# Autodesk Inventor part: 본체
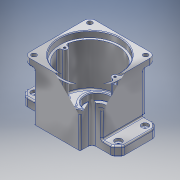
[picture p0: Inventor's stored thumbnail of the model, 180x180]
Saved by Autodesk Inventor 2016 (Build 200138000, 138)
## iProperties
Created: 2017-01
Part Number: 본체
Material: 알루미늄 6061
Document SubType Name: Modeling
Designer: Owner
Density: 2.7 g/cm^3
Appearance: 알루미늄 - 평지
Mass: 877.431 g
Surface Area: 768.445 cm^2
Volume: 324.975 cm^3
Author: Owner
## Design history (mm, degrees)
sketch "스케치1"
  geometry: L1 (-33, 47)-(33, 47); L2 (33, 47)-(33, -47); L3 (33, -47)-(-33, -47); L4 (-33, -47)-(-33, 47); L5 (-33, 47)-(33, -47); L6 (33, 47)-(-33, -47); 1 further point
  constraints: 12 end point, 2 midpoint, 2 parallel, 1 horizontal, 1 perpendicular
  dimensions: "d0" = 66 distance of L2.end L3.end; "d1" = 94 distance of L1.end L2.end
extrude "돌출1" new body sketch "스케치1" distance "d2" = 80; taper "d3" = 0 deg
sketch "스케치2"
  geometry: L1 (-33, 0)-(-33, 80) reference; L2 (-33, 0)-(-70, 0); L3 (-70, 0)-(-70, 13); L4 (-70, 13)-(-47, 13); L5 (-47, 13)-(-47, 70); L6 (-47, 70)-(-33, 70); 1 further point
  constraints: 10 end point, 4 perpendicular, 1 horizontal, 1 point on line
  dimensions: "d4" = 70 distance between parallel lines of L6 L2; "d5" = 13 distance between parallel lines of L2 L4; "d6" = 70 distance from line of L3 point (0, 0); "d7" = 47 distance from line of point (0, 0) L5
extrude "돌출2" join sketch "스케치2" stored distance "d8" = 60; taper "d9" = 0 deg
sketch "스케치3"
  geometry: L1 (-47, 47)-(47, 47); L2 (47, 47)-(47, -47); L3 (47, -47)-(-47, -47); L4 (-47, -47)-(-47, 47); L5 (-47, 47)-(47, -47); L6 (47, 47)-(-47, -47); 1 further point
  constraints: 12 end point, 2 midpoint, 2 parallel, 1 horizontal, 1 perpendicular
  dimensions: "d10" = 94 distance of L2.end L3.end; "d11" = 94 distance of L1.end L2.end
extrude "돌출3" join sketch "스케치3" distance "d12" = 10; taper "d13" = 0 deg
fillet "모깎기1" dims "d14" = 8
chamfer "모따기1" distance "d15" = 8; stored, may be unused: second distance "d16" = 2, angle "d17" = 45 deg
fillet "모깎기2" dims "d32" = 5
fillet "모깎기3" dims "d33" = 5
node "작업 평면1"
sketch "스케치5"
  geometry: L1 (-60, 19)-(60, 19); L2 (60, 19)-(60, -19); L3 (60, -19)-(-60, -19); L4 (-60, -19)-(-60, 19); L5 (-60, 19)-(60, -19); L6 (60, 19)-(-60, -19); 5 further points
  constraints: 12 end point, 4 coincident, 2 midpoint, 2 parallel, 1 horizontal, 1 perpendicular
  dimensions: "d35" = 120 distance of L2.end L3.end; "d36" = 38 distance of L1.end L2.end
hole "구멍1" sketch "스케치5" at (-60, 19), (60, -19), (60, 19), (-60, -19) diameter "d37" = 4; stored, may be unused: countersink angle "d41" = 90 deg, drill point angle "d43" = 118 deg; dims "d38" = 6, "d39" = 10, "d40" = 4, "d42" = 8
sketch "스케치6"
  geometry: C1 r 43 at (0, 0); 1 further point
  constraints: 1 centre point, 1 coincident
  dimensions: "d53" = 86 diameter of C1
extrude "돌출5" cut sketch "스케치6" distance "d54" = 9; taper "d55" = 0 deg
sketch "스케치7"
  geometry: C1 r 40 at (0, 0); 1 further point
  constraints: 1 centre point, 1 coincident
  dimensions: "d56" = 80 diameter of C1
extrude "돌출6" cut sketch "스케치7" distance "d57" = 62; taper "d58" = 0 deg
sketch "스케치9"
  geometry: L1 (-38, -30)-(-59.929, -30) reference; L2 (-33, -35)-(-33, -47) reference; L3 (-33, -47)-(33, -47) reference; L4 (33, -47)-(33, -35) reference; L5 (38, -30)-(59.929, -30) reference; L6 (68.536, -23.464)-(63.464, -28.536) reference; L7 (70, -19.929)-(70, 19.929) reference; L8 (63.464, 28.536)-(68.536, 23.464) reference; L9 (59.929, 30)-(38, 30) reference; L10 (33, 35)-(33, 47) reference; L11 (33, 47)-(-33, 47) reference; L12 (-33, 47)-(-33, 35) reference; L13 (-59.929, 30)-(-38, 30) reference; L14 (-68.536, 23.464)-(-63.464, 28.536) reference; L15 (-70, -19.929)-(-70, 19.929) reference; L16 (-63.464, -28.536)-(-68.536, -23.464) reference; L17 (-32, 46)-(32, 46); L18 (32, 46)-(32, 35); L19 (38, 29)-(59.929, 29); L20 (62.757, 27.828)-(67.828, 22.757); L21 (69, 19.929)-(69, -19.929); L22 (67.828, -22.757)-(62.757, -27.828); L23 (59.929, -29)-(38, -29); L24 (32, -35)-(32, -46); L25 (32, -46)-(-32, -46); L26 (-32, -46)-(-32, -35); L27 (-38, -29)-(-59.929, -29); L28 (-62.757, -27.828)-(-67.828, -22.757); L29 (-69, -19.929)-(-69, 19.929); L30 (-67.828, 22.757)-(-62.757, 27.828); L31 (-59.929, 29)-(-38, 29); L32 (-32, 35)-(-32, 46); C1 r 2 at (-60, 19) reference; C2 r 2 at (60, 19) reference; C3 r 2 at (-60, -19) reference; C4 r 2 at (60, -19) reference; A1 r 5 centre (-59.929, -25) between (-63.464, -28.536) and (-59.929, -30) reference; A2 r 5 centre (-38, -35) between (-33, -35) and (-38, -30) reference; A3 r 5 centre (38, -35) between (38, -30) and (33, -35) reference; A4 r 5 centre (59.929, -25) between (59.929, -30) and (63.464, -28.536) reference; A5 r 5 centre (65, -19.929) between (68.536, -23.464) and (70, -19.929) reference; A6 r 5 centre (65, 19.929) between (70, 19.929) and (68.536, 23.464) reference; A7 r 5 centre (59.929, 25) between (63.464, 28.536) and (59.929, 30) reference; A8 r 5 centre (38, 35) between (33, 35) and (38, 30) reference; A9 r 5 centre (-38, 35) between (-38, 30) and (-33, 35) reference; A10 r 5 centre (-59.929, 25) between (-59.929, 30) and (-63.464, 28.536) reference; A11 r 5 centre (-65, 19.929) between (-68.536, 23.464) and (-70, 19.929) reference; A12 r 5 centre (-65, -19.929) between (-70, -19.929) and (-68.536, -23.464) reference; A13 r 6 centre (38, 35) between (32, 35) and (38, 29); A14 r 4 centre (59.929, 25) between (62.757, 27.828) and (59.929, 29); A15 r 4 centre (65, 19.929) between (69, 19.929) and (67.828, 22.757); A16 r 4 centre (65, -19.929) between (67.828, -22.757) and (69, -19.929); A17 r 4 centre (59.929, -25) between (59.929, -29) and (62.757, -27.828); A18 r 6 centre (38, -35) between (38, -29) and (32, -35); A19 r 6 centre (-38, -35) between (-32, -35) and (-38, -29); A20 r 4 centre (-59.929, -25) between (-62.757, -27.828) and (-59.929, -29); A21 r 4 centre (-65, -19.929) between (-69, -19.929) and (-67.828, -22.757); A22 r 4 centre (-65, 19.929) between (-67.828, 22.757) and (-69, 19.929); A23 r 4 centre (-59.929, 25) between (-59.929, 29) and (-62.757, 27.828); A24 r 6 centre (-38, 35) between (-38, 29) and (-32, 35); 1 further point
  constraints: 32 end point, 24 point on circle, 12 centre point, 27 other
  dimensions: "d66" = 1 distance between parallel lines of L11 L17
extrude "돌출7" cut sketch "스케치9" distance "d67" = 1; taper "d68" = 0 deg
sketch "스케치10"
  geometry: C1 r 21 at (0, 11); C2 r 15 at (0, -22); 1 further point
  constraints: 2 centre point, 2 vertical alignment
  dimensions: "d69" = 42 diameter of C1; "d70" = 30 diameter of C2; "d71" = 11 distance of point (0, 0) C1.centre; "d72" = 22 distance of point (0, 0) C2.centre
extrude "돌출8" join sketch "스케치10" distance "d73" = 7; taper "d74" = 0 deg
sketch "스케치11"
  geometry: C1 r 27.5 at (0, 11); 1 further point
  constraints: 1 centre point, 1 vertical alignment
  dimensions: "d75" = 55 diameter of C1; "d76" = 11 distance of point (0, 0) C1.centre
extrude "돌출9" join sketch "스케치11" distance "d77" = 7; taper "d78" = 0 deg
sketch "스케치12"
  geometry: L1 (11, -7)-(11, 16); L2 (23.5, 1)-(27, 1); L3 (28.5, 16)-(28.5, 6); L4 (28.5, 6)-(23.5, 6); L5 (23.5, 6)-(23.5, 1); L6 (27, 1)-(27, -7); L7 (-16.5, -7)-(38.5, -7) reference; L8 (27, -7)-(11, -7); L9 (28.5, 16)-(11, 16); L10 (32, 16)-(-8.773, 16) reference; 1 further point
  constraints: 16 end point, 3 vertical, 2 midpoint, 2 perpendicular, 1 collinear, 1 horizontal, 1 point on line
  dimensions: "d79" = 11 distance from line of point (0, 0) L1; "d80" = 23 distance of L1.start L1.end; "d81" = 8 distance of L2.end L6.end; "d82" = 5 distance of L4.end L2.start; "d83" = 25 diameter of L5 L1; "d85" = 35 diameter of L3 L1; "d86" = 32 diameter of L6 L1
revolve "회전1" sketch "스케치12" stored, may be unused: angle "d87" = 90 deg
sketch "스케치13"
  geometry: L1 (-20, 16)-(-20, 8); L2 (-8.773, 16)-(-37, 16) reference; L3 (-20, 16)-(-31, 16); L4 (-31, 16)-(-31, 9); L5 (-31, 9)-(-29.5, 9); L6 (-29.5, 8)-(-20, 8); L7 (-29.5, 8)-(-29.5, 9); 1 further point
  constraints: 12 end point, 3 vertical, 2 point on line, 1 parallel
  dimensions: "d88" = 8 distance of L1.start L1.end; "d89" = 20 distance from line of point (0, 0) L1; "d90" = 22 diameter of L4 L1; "d91" = 19 diameter of L7 L1; "d92" = 1 distance of L6.start L5.end; "d93" = 7 distance of L3.end L4.end
revolve "회전2" sketch "스케치13" stored, may be unused: angle "d94" = 90 deg
sketch "스케치14"
  geometry: A1 r 40 centre (0, 0) between (39.148, 8.214) and (39.148, -8.214) reference; A2 r 4 centre (36, 0) between (35.852, 3.997) and (35.852, -3.997); A3 r 3.5 centre (35.722, 7.495) between (35.852, 3.997) and (39.148, 8.214); A4 r 3.5 centre (35.722, -7.495) between (39.148, -8.214) and (35.852, -3.997); 1 further point
  constraints: 8 point on circle, 5 tangent, 3 centre point, 1 horizontal alignment
  dimensions: "d95" = 8 diameter of A2; "d96" = 7 diameter of A3; "d97" = 7 diameter of A4
extrude "돌출10" join sketch "스케치14" stored distance "d98" = 7; taper "d99" = 0 deg
hole "구멍3" diameter "d102" = 3.242; stored, may be unused: countersink angle "d106" = 90 deg, drill point angle "d108" = 118 deg; dims "d100" = 10, "d101" = 10, "d103" = 7, "d104" = 4, "d105" = 2, "d107" = 9
chamfer "모따기2" distance "d111" = 1; stored, may be unused: second distance "d112" = 2, angle "d113" = 45 deg
fillet "모깎기4" dims "d114" = 0.3
fillet "모깎기5" dims "d115" = 3
sketch "스케치15"
  geometry: L1 (-40, 40)-(40, 40); L2 (40, 40)-(40, -40); L3 (40, -40)-(-40, -40); L4 (-40, -40)-(-40, 40); L5 (-40, 40)-(40, -40); L6 (40, 40)-(-40, -40); 5 further points
  constraints: 12 end point, 4 coincident, 2 midpoint, 2 parallel, 1 horizontal, 1 perpendicular
  dimensions: "d116" = 80 distance of L2.end L3.end; "d117" = 80 distance of L1.end L2.end
hole "구멍4" sketch "스케치15" at (-40, 40), (-40, -40), (40, -40), (40, 40) diameter "d118" = 7; stored, may be unused: countersink angle "d122" = 90 deg, drill point angle "d124" = 118 deg; dims "d119" = 7, "d120" = 4, "d121" = 2, "d123" = 9
fillet "모깎기6" dims "d125" = 2
fillet "모깎기7" dims "d126" = 2
fillet "모깎기8" dims "d127" = 2
fillet "모깎기9" dims "d128" = 2
fillet "모깎기10" dims "d129" = 1
sketch "스케치16"
  geometry: L1 (0, 0)-(78, 0) reference; 2 further points
  constraints: 1 vertical alignment, 1 other
  dimensions: "d130" = 40 distance from line of L1 point (39, 40)
feature "엠보싱1" sketch "스케치16" dims "d131" = 0.5, "d132" = 0
fillet "모깎기11" dims "d133" = 2
fillet "모깎기12" dims "d134" = 2
fillet "모깎기13" dims "d135" = 2
node "솔리드1"
mirror "대칭1"
mirror "대칭4"
node "투영된 루프1"
other parameters: "d34" = 13
